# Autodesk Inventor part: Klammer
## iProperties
Shininess: 64.0
Length Units: 11269
Angle Units: 11279
Time Units: 11290
Mass Units: 11283
Length Display Precision: 3
Angle Display Precision: 2
Compacted: True
Part Number: Klammer
Document SubType Name: Modeling
Created: 2004-08
Material: Standard
Designer: mp
Manufacturer: Standard
Standards Organization: Custom
Density: 0.0
Volumn: 0.0
Area: 0.0
PropertySet Name: Model Information
Control State: 0
Master: False
Checked Out: False
Author: mp
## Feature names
1. Extrusion1
